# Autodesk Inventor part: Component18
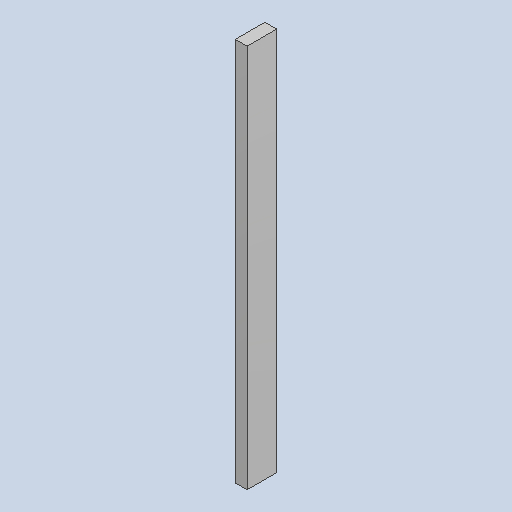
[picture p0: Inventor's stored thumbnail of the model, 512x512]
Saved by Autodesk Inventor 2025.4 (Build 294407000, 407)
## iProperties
Created: 2026-06
Part Number: Component18
Material: Generic
Document SubType Name: Modeling
Designer: AdminForWorker
Density: 1 g/cm^3
Appearance: Default
Title: Component18
Author: AdminForWorker
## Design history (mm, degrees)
feature "Body1"
body "Solid1"
